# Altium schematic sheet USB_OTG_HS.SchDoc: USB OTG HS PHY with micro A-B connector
size A4; Author: N.P; CompanyName: STMicroelectronics; Organization: MCD/APPLIS/LMS; DocumentNumber: MB1260; SheetNumber: 8; SheetTotal: 13; Project: STM32F723e-DISCO
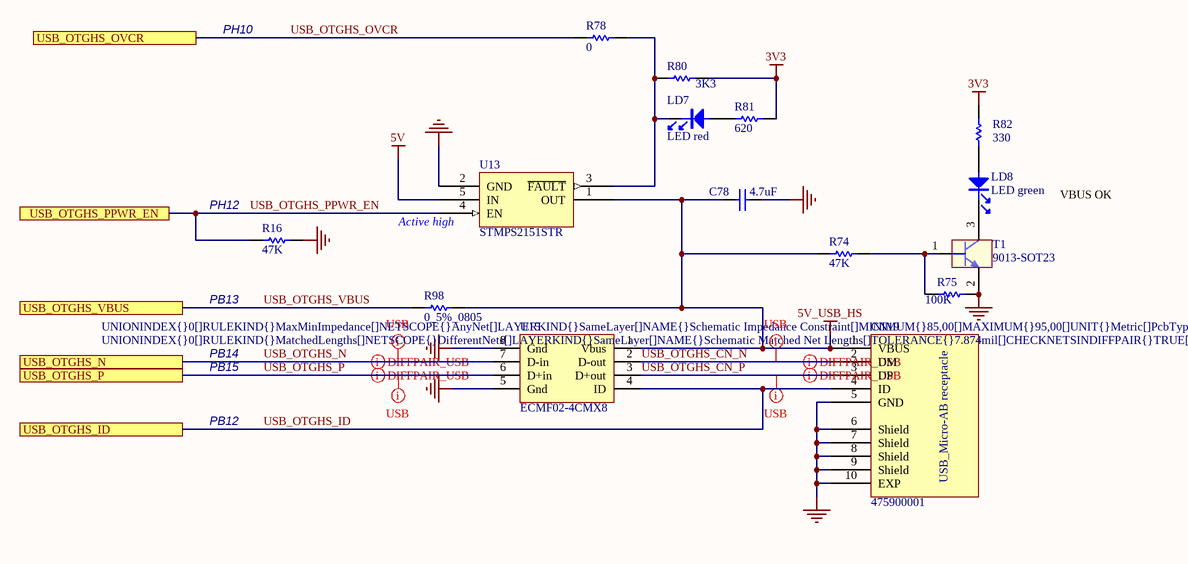
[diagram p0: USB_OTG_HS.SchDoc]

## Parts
C78  4.7uF  [0603C]
CN19  475900001  [MOLEX_47590001]
LD7  LED red  [0603D]
LD8  LED green  [0603D]
R16  value 47K  [0402R]  (hidden comment: 47K_1%_0402)
R74  value 47K  [0402R]  (hidden comment: 47K_1%_0402)
R75  value 100K  [0402R]  (hidden comment: 100K_1%_0402)
R78  0  [0402R]
R80  3K3  [0402R]
R81  value 620  [0603R]  (hidden comment: 620_1%_0603)
R82  value 330  [0603R]  (hidden comment: 330_1%_0603)
R98  0_5%_0805  [0805R]
T1  9013-SOT23  [SOT-23]
U13  STMPS2151STR  [SOT23-5]
U15  ECMF02-4CMX8  [QFN8_0R5_2R5X1R2]

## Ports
USB_OTGHS_ID, USB_OTGHS_N, USB_OTGHS_OVCR, USB_OTGHS_P, USB_OTGHS_PPWR_EN, USB_OTGHS_VBUS

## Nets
3V3: R80.1 R81.1 R82.2
5V: U13.5(IN)
5V_USB_HS: C78.1 CN19.1(VBUS) R74.2 R98.2 U13.1(OUT) U15.1(Vbus)
GND: C78.2 CN19.5(GND) CN19.6(Shield) CN19.7(Shield) CN19.8(Shield) CN19.9(Shield) CN19.10(EXP) R16.1 R75.2 T1.2(E) U13.2(GND) U15.5(Gnd) U15.8(Gnd)
USB_OTGHS_CN_N: CN19.2(DM) U15.2(D-out)
USB_OTGHS_CN_P: CN19.3(DP) U15.3(D+out)
USB_OTGHS_ID: CN19.4(ID) U15.4(ID) ; port USB_OTGHS_ID
USB_OTGHS_N: U15.7(D-in) ; port USB_OTGHS_N
USB_OTGHS_OVCR: R78.2 ; port USB_OTGHS_OVCR
USB_OTGHS_P: U15.6(D+in) ; port USB_OTGHS_P
USB_OTGHS_PPWR_EN: R16.2 U13.4(EN) ; port USB_OTGHS_PPWR_EN
USB_OTGHS_VBUS: R98.1 ; port USB_OTGHS_VBUS
NetLD7_1: LD7.1 R81.2
NetLD7_2: LD7.2 R78.1 R80.2 U13.3(~{FAULT})
NetLD8_1: LD8.1 R82.1
NetLD8_2: LD8.2 T1.3(C)
NetR74_1: R74.1 R75.1 T1.1(B)

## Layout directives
differential pair; rule Impedance Constraint [Min = 85.00    Max = 95.00    ]: USB_OTGHS_CN_N, USB_OTGHS_CN_P, USB_OTGHS_N, USB_OTGHS_P
rule Undefined; rule Matched Net Lengths [Tolerance = 0.2mm]; rule Impedance Constraint [Min = 85.00    Max = 95.00    ]: USB_OTGHS_CN_N, USB_OTGHS_CN_P, USB_OTGHS_N, USB_OTGHS_P

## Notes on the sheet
- PH10
- (near R16) PH12
- VBUS OK
- (near U13) Active high
- PB13
- PB14
- PB15
- PB12

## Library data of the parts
C78 = Cap_4.7uF_X5R_10%_0603: Capacitor,4.7uF,16V, X5R,10%,0603,YAGEO; Manuf_Part_1: CC0603KRX5R7BB475; Order: CC0603KRX5R7BB105; Ordered by: Subcon; Fitted: YES
CN19 = 475900001: USB-MICRO-AB, 47590-0001, SMT, MOLEX; Ordered by: Subcon; Fitted: YES
LD7 = LED_red: LED red 0603; Manuf_1: everlight; Manuf_Part_1: 19-213-R6C-AP1Q2B/3T; Ordered by: Subcon; Fitted: YES
LD8 = LED_green: LED green 0603; Manuf_1: everlight; Manuf_Part_1: 19-213SYGC/S530-E2/TR8; Ordered by: Subcon; Fitted: YES
R16 R74 = Res_47K_1%_0402: Resistor,47K,0402,1%,YAGEO; Manuf_Part_1: RC0402FR-0747KL; Order: 9239430; Ordered by: Subcon; Fitted: YES
R75 = Res_100K_1%_0402: Resistor,100K,0402,1%,YAGEO; Manuf_Part_1: RC0402FR-07100KL; Manuf_Part_2: RT0402FRE07100KL; Ordered by: Subcon; Fitted: YES
R78 = Res_0_5%_0402: Resistor,0,0402,5%,YAGEO; Manuf_Part_1: RC0402JR-070RL; Order: 2363467; Ordered by: Subcon; Fitted: YES
R80 = Res_3K3_1%_0402: Resistor,3K3,0402,1%,YAGEO; Manuf_Part_1: RC0402FR-073K3L; Ordered by: Subcon; Fitted: YES
R81 = Res_620_1%_0603: Resistor,620,0603,1%,VISHAY; Manuf_Part_1: CRCW0603620RFKEA; Manuf_1: VISHAY DRALORIC; Order: 2122341; Ordered by: Subcon; Fitted: YES
R82 = Res_330_1%_0603: Resistor,330,0603,1%,YAGEO; Manuf_Part_1: RC0603FR-07330RL; Manuf_Part_2: RT0603FRE07330RL; Ordered by: Subcon; Fitted: YES
R98 = Res_0_5%_0805: Resistor,0,0805,5%,YAGEO; Manuf_Part_1: RC0805JR-070RL; Value: 0; Order: 2363489; Fitted: YES; Ordered by: Subcon
T1 = 9013-SOT23: NPN Bipolar Transistor; Manuf_1: NXP; Manuf_Part_1: BSR14; Order: 1081310; Ordered by: Subcon; Fitted: YES
U13 = STMPS2151STR: Enhanced single channel power switches; Manuf_1: STM; Provided: ST; ECCN_US/EU: EAR99/NEC; Fitted: YES
U15 = ECMF02-4CMX8: Common mode filter with ESD protection for USB 2.0 interface; Manuf_1: STM; Provided: ST; ECCN_US/EU: EAR99/NEC; Fitted: YES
